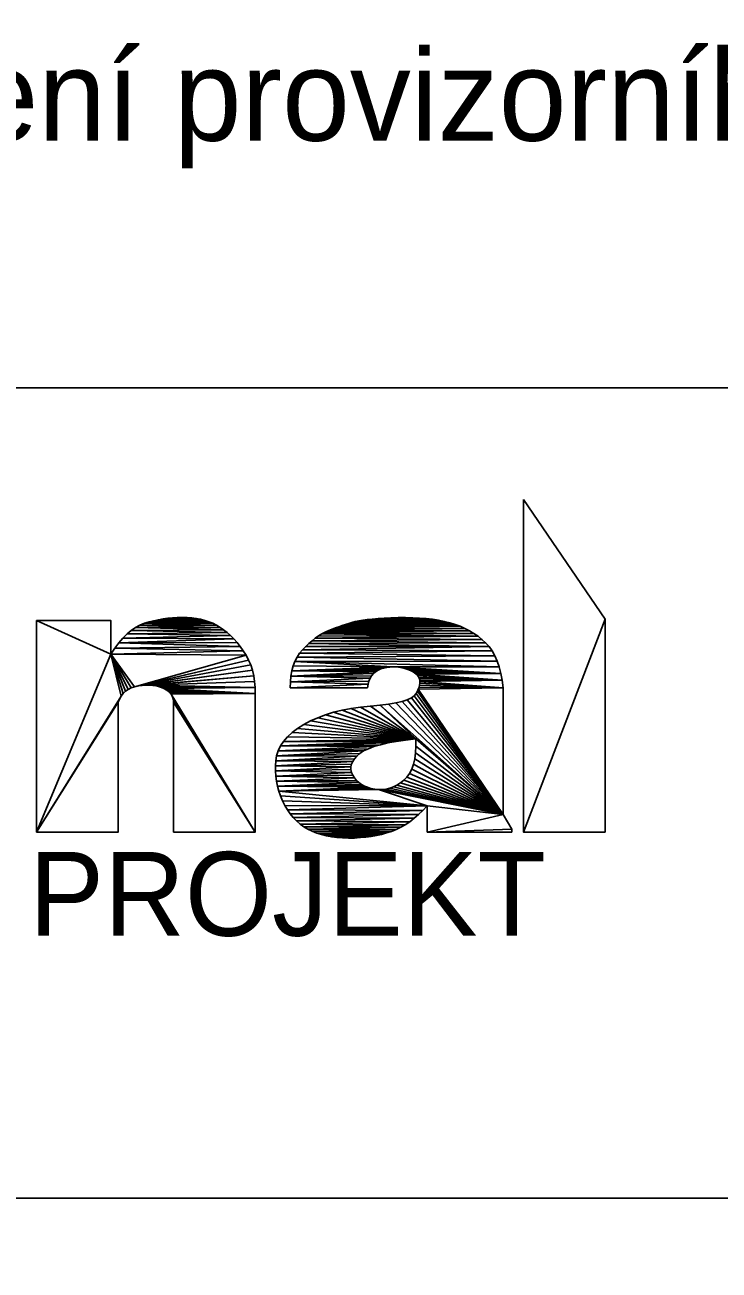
# Model space of a CAD drawing. Extents: x -630 to 5777, y 50 to 2087.
# Drawn here: x -160.3 to -141.25, y 88.03 to 122.18 of the extents above; entities that cross this region are included whole.
import ezdxf

# ---------------------------------------------------------------- set-up
doc = ezdxf.new("R2010")
doc.units = 0
doc.layers.add('Vrstva 1', color=7, linetype='Continuous')
doc.layers.add('Vrstva 50', color=7, linetype='Continuous')

msp = doc.modelspace()

# ---------------------------------------------------------------- linework, layer by layer
for points in [[(-180, 112.226), (-15, 112.226), (-15, 60), (-180, 60)], [(-146.62, 109.158), (-146.62, 100.038), (-144.38, 105.878)], [(-156.509, 105.886), (-156.638, 105.864), (-155.478, 105.876)], [(-155.478, 105.876), (-156.638, 105.864), (-155.363, 105.846)], [(-156.379, 105.904), (-156.509, 105.886), (-155.597, 105.9)], [(-155.597, 105.9), (-156.509, 105.886), (-155.478, 105.876)], [(-156.247, 105.918), (-156.379, 105.904), (-155.721, 105.916)], [(-155.721, 105.916), (-156.379, 105.904), (-155.597, 105.9)], [(-156.115, 105.926), (-156.247, 105.918), (-155.721, 105.916)], [(-155.981, 105.928), (-156.115, 105.926), (-155.849, 105.926)], [(-155.849, 105.926), (-156.115, 105.926), (-155.721, 105.916)], [(-150.905, 105.868), (-151.03, 105.85), (-148.953, 105.848)], [(-150.766, 105.882), (-150.905, 105.868), (-149.119, 105.874)], [(-149.119, 105.874), (-150.905, 105.868), (-148.953, 105.848)], [(-150.611, 105.896), (-150.766, 105.882), (-149.293, 105.894)], [(-149.293, 105.894), (-150.766, 105.882), (-149.119, 105.874)], [(-150.442, 105.906), (-150.611, 105.896), (-149.293, 105.894)], [(-150.258, 105.914), (-150.442, 105.906), (-149.474, 105.91)], [(-149.474, 105.91), (-150.442, 105.906), (-149.293, 105.894)], [(-150.059, 105.92), (-150.258, 105.914), (-149.661, 105.918)], [(-149.661, 105.918), (-150.258, 105.914), (-149.474, 105.91)], [(-149.857, 105.922), (-150.059, 105.92), (-149.661, 105.918)], [(-144.38, 105.878), (-146.62, 100.038), (-144.38, 100.038)], [(-157.94, 104.918), (-157.94, 105.838), (-159.98, 105.838)], [(-159.98, 105.838), (-159.98, 100.038), (-157.94, 104.918)], [(-157.382, 105.57), (-157.498, 105.472), (-154.752, 105.512)], [(-157.263, 105.652), (-157.382, 105.57), (-154.847, 105.586)], [(-154.847, 105.586), (-157.382, 105.57), (-154.752, 105.512)], [(-157.142, 105.716), (-157.263, 105.652), (-155.044, 105.712)], [(-155.044, 105.712), (-157.263, 105.652), (-154.944, 105.654)], [(-154.944, 105.654), (-157.263, 105.652), (-154.847, 105.586)], [(-155.146, 105.764), (-157.142, 105.716), (-155.044, 105.712)], [(-157.018, 105.764), (-157.142, 105.716), (-155.146, 105.764)], [(-156.892, 105.802), (-157.018, 105.764), (-155.146, 105.764)], [(-156.766, 105.836), (-156.892, 105.802), (-155.252, 105.808)], [(-155.252, 105.808), (-156.892, 105.802), (-155.146, 105.764)], [(-156.638, 105.864), (-156.766, 105.836), (-155.363, 105.846)], [(-155.363, 105.846), (-156.766, 105.836), (-155.252, 105.808)], [(-152.058, 105.524), (-152.15, 105.476), (-147.98, 105.486)], [(-151.965, 105.566), (-152.058, 105.524), (-148.1, 105.558)], [(-148.1, 105.558), (-152.058, 105.524), (-147.98, 105.486)], [(-151.871, 105.602), (-151.965, 105.566), (-148.1, 105.558)], [(-151.779, 105.638), (-151.871, 105.602), (-148.226, 105.624)], [(-148.226, 105.624), (-151.871, 105.602), (-148.1, 105.558)], [(-151.687, 105.672), (-151.779, 105.638), (-148.226, 105.624)], [(-151.595, 105.702), (-151.687, 105.672), (-148.358, 105.682)], [(-148.358, 105.682), (-151.687, 105.672), (-148.226, 105.624)], [(-151.505, 105.732), (-151.595, 105.702), (-148.358, 105.682)], [(-151.415, 105.76), (-151.505, 105.732), (-148.497, 105.734)], [(-148.497, 105.734), (-151.505, 105.732), (-148.358, 105.682)], [(-151.325, 105.786), (-151.415, 105.76), (-148.642, 105.778)], [(-148.642, 105.778), (-151.415, 105.76), (-148.497, 105.734)], [(-151.237, 105.81), (-151.325, 105.786), (-148.642, 105.778)], [(-151.141, 105.832), (-151.237, 105.81), (-148.794, 105.816)], [(-148.794, 105.816), (-151.237, 105.81), (-148.642, 105.778)], [(-151.03, 105.85), (-151.141, 105.832), (-148.953, 105.848)], [(-148.953, 105.848), (-151.141, 105.832), (-148.794, 105.816)], [(-157.724, 105.228), (-157.833, 105.082), (-154.393, 105.128)], [(-157.612, 105.358), (-157.724, 105.228), (-154.568, 105.336)], [(-154.568, 105.336), (-157.724, 105.228), (-154.479, 105.236)], [(-154.479, 105.236), (-157.724, 105.228), (-154.393, 105.128)], [(-157.498, 105.472), (-157.612, 105.358), (-154.659, 105.428)], [(-154.659, 105.428), (-157.612, 105.358), (-154.568, 105.336)], [(-154.752, 105.512), (-157.498, 105.472), (-154.659, 105.428)], [(-152.509, 105.212), (-152.596, 105.13), (-147.565, 105.126)], [(-152.421, 105.288), (-152.509, 105.212), (-147.658, 105.23)], [(-147.658, 105.23), (-152.509, 105.212), (-147.565, 105.126)], [(-152.332, 105.358), (-152.421, 105.288), (-147.759, 105.322)], [(-147.759, 105.322), (-152.421, 105.288), (-147.658, 105.23)], [(-152.242, 105.42), (-152.332, 105.358), (-147.866, 105.408)], [(-147.866, 105.408), (-152.332, 105.358), (-147.759, 105.322)], [(-152.15, 105.476), (-152.242, 105.42), (-147.866, 105.408)], [(-147.98, 105.486), (-152.15, 105.476), (-147.866, 105.408)], [(-157.94, 104.918), (-159.98, 100.038), (-157.662, 103.77)], [(-157.833, 105.082), (-157.94, 104.918), (-154.308, 105.012)], [(-154.308, 105.012), (-157.94, 104.918), (-154.229, 104.888)], [(-157.94, 104.918), (-157.291, 104.024), (-154.229, 104.888)], [(-157.94, 104.918), (-157.385, 103.994), (-157.291, 104.024)], [(-157.94, 104.918), (-157.469, 103.952), (-157.385, 103.994)], [(-157.94, 104.918), (-157.543, 103.902), (-157.469, 103.952)], [(-157.94, 104.918), (-157.607, 103.84), (-157.543, 103.902)], [(-157.94, 104.918), (-157.662, 103.77), (-157.607, 103.84)], [(-154.393, 105.128), (-157.833, 105.082), (-154.308, 105.012)], [(-154.229, 104.888), (-157.291, 104.024), (-154.161, 104.758)], [(-152.763, 104.942), (-152.832, 104.836), (-147.407, 104.876)], [(-147.407, 104.876), (-152.832, 104.836), (-147.343, 104.73)], [(-152.682, 105.04), (-152.763, 104.942), (-147.481, 105.008)], [(-147.481, 105.008), (-152.763, 104.942), (-147.407, 104.876)], [(-152.596, 105.13), (-152.682, 105.04), (-147.565, 105.126)], [(-147.565, 105.126), (-152.682, 105.04), (-147.481, 105.008)], [(-154.161, 104.758), (-157.291, 104.024), (-157.187, 104.046)], [(-154.161, 104.758), (-157.187, 104.046), (-154.104, 104.622)], [(-154.104, 104.622), (-157.187, 104.046), (-154.058, 104.478)], [(-152.938, 104.594), (-152.975, 104.46), (-150.209, 104.57)], [(-150.209, 104.57), (-152.975, 104.46), (-150.291, 104.566)], [(-150.291, 104.566), (-152.975, 104.46), (-150.373, 104.554)], [(-150.373, 104.554), (-152.975, 104.46), (-150.454, 104.536)], [(-150.454, 104.536), (-152.975, 104.46), (-150.535, 104.512)], [(-150.535, 104.512), (-152.975, 104.46), (-150.611, 104.48)], [(-152.89, 104.72), (-152.938, 104.594), (-150.209, 104.57)], [(-152.832, 104.836), (-152.89, 104.72), (-147.343, 104.73)], [(-147.343, 104.73), (-152.89, 104.72), (-147.288, 104.568)], [(-152.89, 104.72), (-150.209, 104.57), (-147.288, 104.568)], [(-150.209, 104.57), (-150.127, 104.568), (-147.288, 104.568)], [(-150.127, 104.568), (-150.044, 104.56), (-147.288, 104.568)], [(-147.288, 104.568), (-150.044, 104.56), (-147.243, 104.392)], [(-150.044, 104.56), (-149.96, 104.546), (-147.243, 104.392)], [(-149.96, 104.546), (-149.876, 104.524), (-147.243, 104.392)], [(-149.876, 104.524), (-149.796, 104.498), (-147.243, 104.392)], [(-154.058, 104.478), (-157.187, 104.046), (-157.081, 104.058)], [(-154.058, 104.478), (-157.081, 104.058), (-154.022, 104.328)], [(-154.022, 104.328), (-157.081, 104.058), (-156.98, 104.066)], [(-154.022, 104.328), (-156.98, 104.066), (-156.885, 104.066)], [(-154.022, 104.328), (-156.885, 104.066), (-153.998, 104.17)], [(-153.998, 104.17), (-156.885, 104.066), (-153.984, 104.008)], [(-153.016, 104.16), (-153.02, 103.998), (-150.885, 104.094)], [(-153.001, 104.314), (-153.016, 104.16), (-150.828, 104.26)], [(-150.828, 104.26), (-153.016, 104.16), (-150.861, 104.182)], [(-150.861, 104.182), (-153.016, 104.16), (-150.885, 104.094)], [(-152.975, 104.46), (-153.001, 104.314), (-150.678, 104.438)], [(-150.678, 104.438), (-153.001, 104.314), (-150.737, 104.388)], [(-150.737, 104.388), (-153.001, 104.314), (-150.787, 104.328)], [(-150.787, 104.328), (-153.001, 104.314), (-150.828, 104.26)], [(-150.611, 104.48), (-152.975, 104.46), (-150.678, 104.438)], [(-149.796, 104.498), (-149.724, 104.47), (-147.243, 104.392)], [(-149.724, 104.47), (-149.662, 104.44), (-147.243, 104.392)], [(-149.662, 104.44), (-149.608, 104.408), (-147.243, 104.392)], [(-149.608, 104.408), (-149.563, 104.374), (-147.243, 104.392)], [(-147.243, 104.392), (-149.563, 104.374), (-147.207, 104.202)], [(-149.563, 104.374), (-149.526, 104.338), (-147.207, 104.202)], [(-149.526, 104.338), (-149.499, 104.3), (-147.207, 104.202)], [(-149.499, 104.3), (-149.48, 104.26), (-147.207, 104.202)], [(-149.48, 104.26), (-149.468, 104.216), (-147.207, 104.202)], [(-149.468, 104.216), (-149.463, 104.17), (-147.207, 104.202)], [(-149.463, 104.17), (-149.464, 104.122), (-147.18, 103.998)], [(-147.207, 104.202), (-149.463, 104.17), (-147.18, 103.998)], [(-156.885, 104.066), (-156.794, 104.062), (-153.984, 104.008)], [(-156.794, 104.062), (-156.709, 104.05), (-153.984, 104.008)], [(-156.709, 104.05), (-156.63, 104.032), (-153.984, 104.008)], [(-156.63, 104.032), (-156.555, 104.008), (-153.984, 104.008)], [(-156.555, 104.008), (-156.486, 103.978), (-153.984, 104.008)], [(-153.984, 104.008), (-156.486, 103.978), (-153.98, 103.838)], [(-156.486, 103.978), (-156.424, 103.944), (-153.98, 103.838)], [(-156.424, 103.944), (-156.37, 103.906), (-153.98, 103.838)], [(-156.37, 103.906), (-156.324, 103.864), (-153.98, 103.838)], [(-156.324, 103.864), (-156.287, 103.818), (-153.98, 103.838)], [(-153.98, 103.838), (-156.287, 103.818), (-153.98, 100.038)], [(-156.287, 103.818), (-156.258, 103.768), (-153.98, 100.038)], [(-150.885, 104.094), (-153.02, 103.998), (-150.9, 103.998)], [(-149.564, 103.838), (-149.615, 103.776), (-147.18, 100.518)], [(-149.532, 103.9), (-149.564, 103.838), (-147.18, 100.518)], [(-149.506, 103.96), (-149.532, 103.9), (-147.18, 100.518)], [(-149.486, 104.016), (-149.506, 103.96), (-147.18, 103.998)], [(-147.18, 103.998), (-149.506, 103.96), (-147.18, 100.518)], [(-149.472, 104.07), (-149.486, 104.016), (-147.18, 103.998)], [(-149.464, 104.122), (-149.472, 104.07), (-147.18, 103.998)], [(-157.662, 103.77), (-159.98, 100.038), (-157.706, 103.688)], [(-157.706, 103.688), (-159.98, 100.038), (-157.74, 103.598)], [(-157.74, 103.598), (-159.98, 100.038), (-157.74, 100.038)], [(-156.258, 103.768), (-156.237, 103.716), (-153.98, 100.038)], [(-156.237, 103.716), (-156.225, 103.658), (-153.98, 100.038)], [(-156.225, 103.658), (-156.22, 103.598), (-153.98, 100.038)], [(-156.22, 103.598), (-156.22, 100.038), (-153.98, 100.038)], [(-150.819, 103.496), (-151.091, 103.468), (-149.576, 102.594)], [(-150.556, 103.52), (-150.819, 103.496), (-149.576, 102.594)], [(-150.323, 103.55), (-150.556, 103.52), (-147.18, 100.518)], [(-150.556, 103.52), (-149.576, 102.594), (-147.18, 100.518)], [(-150.121, 103.584), (-150.323, 103.55), (-147.18, 100.518)], [(-149.949, 103.624), (-150.121, 103.584), (-147.18, 100.518)], [(-149.807, 103.67), (-149.949, 103.624), (-147.18, 100.518)], [(-149.696, 103.72), (-149.807, 103.67), (-147.18, 100.518)], [(-149.615, 103.776), (-149.696, 103.72), (-147.18, 100.518)], [(-152.266, 103.176), (-152.464, 103.086), (-149.576, 102.594)], [(-152.055, 103.256), (-152.266, 103.176), (-149.576, 102.594)], [(-151.833, 103.326), (-152.055, 103.256), (-149.576, 102.594)], [(-151.598, 103.384), (-151.833, 103.326), (-149.576, 102.594)], [(-151.35, 103.432), (-151.598, 103.384), (-149.576, 102.594)], [(-151.091, 103.468), (-151.35, 103.432), (-149.576, 102.594)], [(-152.819, 102.878), (-152.967, 102.766), (-149.576, 102.594)], [(-152.65, 102.986), (-152.819, 102.878), (-149.576, 102.594)], [(-152.464, 103.086), (-152.65, 102.986), (-149.576, 102.594)], [(-150.11, 102.526), (-153.287, 102.4), (-150.339, 102.484)], [(-153.201, 102.526), (-153.287, 102.4), (-150.11, 102.526)], [(-150.339, 102.484), (-153.287, 102.4), (-150.544, 102.436)], [(-153.095, 102.648), (-153.201, 102.526), (-149.576, 102.594)], [(-149.576, 102.594), (-153.201, 102.526), (-149.855, 102.562)], [(-149.855, 102.562), (-153.201, 102.526), (-150.11, 102.526)], [(-152.967, 102.766), (-153.095, 102.648), (-149.576, 102.594)], [(-149.576, 102.594), (-149.571, 102.394), (-147.18, 100.518)], [(-153.396, 102.134), (-153.419, 101.994), (-151.191, 102.124)], [(-151.191, 102.124), (-153.419, 101.994), (-151.257, 102.052)], [(-153.352, 102.27), (-153.396, 102.134), (-151.005, 102.264)], [(-151.005, 102.264), (-153.396, 102.134), (-151.108, 102.196)], [(-151.108, 102.196), (-153.396, 102.134), (-151.191, 102.124)], [(-153.287, 102.4), (-153.352, 102.27), (-150.723, 102.384)], [(-150.723, 102.384), (-153.352, 102.27), (-150.876, 102.326)], [(-150.876, 102.326), (-153.352, 102.27), (-151.005, 102.264)], [(-150.544, 102.436), (-153.287, 102.4), (-150.723, 102.384)], [(-149.58, 102.212), (-149.602, 102.046), (-147.18, 100.518)], [(-149.571, 102.394), (-149.58, 102.212), (-147.18, 100.518)], [(-153.419, 101.994), (-153.427, 101.854), (-151.306, 101.978)], [(-151.306, 101.978), (-153.427, 101.854), (-151.338, 101.904)], [(-151.338, 101.904), (-153.427, 101.854), (-151.354, 101.828)], [(-153.427, 101.854), (-153.426, 101.714), (-151.354, 101.828)], [(-151.354, 101.828), (-153.426, 101.714), (-151.353, 101.752)], [(-151.257, 102.052), (-153.419, 101.994), (-151.306, 101.978)], [(-149.636, 101.898), (-149.684, 101.764), (-147.18, 100.518)], [(-149.602, 102.046), (-149.636, 101.898), (-147.18, 100.518)], [(-151.353, 101.752), (-153.426, 101.714), (-151.335, 101.676)], [(-153.426, 101.714), (-153.416, 101.574), (-151.335, 101.676)], [(-151.335, 101.676), (-153.416, 101.574), (-151.301, 101.598)], [(-151.301, 101.598), (-153.416, 101.574), (-151.254, 101.524)], [(-153.416, 101.574), (-153.397, 101.436), (-151.254, 101.524)], [(-151.254, 101.524), (-153.397, 101.436), (-151.199, 101.456)], [(-151.199, 101.456), (-153.397, 101.436), (-151.136, 101.398)], [(-153.397, 101.436), (-153.369, 101.3), (-151.136, 101.398)], [(-149.904, 101.46), (-149.997, 101.388), (-147.18, 100.518)], [(-149.818, 101.544), (-149.904, 101.46), (-147.18, 100.518)], [(-149.744, 101.646), (-149.818, 101.544), (-147.18, 100.518)], [(-149.684, 101.764), (-149.744, 101.646), (-147.18, 100.518)], [(-151.136, 101.398), (-153.369, 101.3), (-151.065, 101.346)], [(-151.065, 101.346), (-153.369, 101.3), (-150.986, 101.302)], [(-150.986, 101.302), (-153.369, 101.3), (-150.9, 101.266)], [(-153.369, 101.3), (-153.332, 101.164), (-150.9, 101.266)], [(-150.9, 101.266), (-153.332, 101.164), (-150.805, 101.238)], [(-150.805, 101.238), (-153.332, 101.164), (-150.702, 101.218)], [(-150.702, 101.218), (-153.332, 101.164), (-150.596, 101.208)], [(-150.596, 101.208), (-153.332, 101.164), (-149.26, 100.758)], [(-153.332, 101.164), (-153.286, 101.03), (-149.26, 100.758)], [(-150.596, 101.208), (-149.26, 100.758), (-147.18, 100.518)], [(-150.492, 101.208), (-150.596, 101.208), (-147.18, 100.518)], [(-150.389, 101.22), (-150.492, 101.208), (-147.18, 100.518)], [(-150.289, 101.246), (-150.389, 101.22), (-147.18, 100.518)], [(-150.19, 101.282), (-150.289, 101.246), (-147.18, 100.518)], [(-150.093, 101.328), (-150.19, 101.282), (-147.18, 100.518)], [(-149.997, 101.388), (-150.093, 101.328), (-147.18, 100.518)], [(-153.286, 101.03), (-153.231, 100.896), (-149.26, 100.758)], [(-153.231, 100.896), (-153.168, 100.768), (-149.26, 100.758)], [(-153.168, 100.768), (-153.098, 100.65), (-149.26, 100.758)], [(-149.26, 100.758), (-153.098, 100.65), (-149.378, 100.634)], [(-149.26, 100.758), (-149.26, 100.038), (-147.18, 100.518)], [(-153.098, 100.65), (-153.021, 100.538), (-149.378, 100.634)], [(-149.378, 100.634), (-153.021, 100.538), (-149.496, 100.52)], [(-153.021, 100.538), (-152.937, 100.438), (-149.496, 100.52)], [(-149.496, 100.52), (-152.937, 100.438), (-149.617, 100.418)], [(-152.937, 100.438), (-152.847, 100.344), (-149.617, 100.418)], [(-149.617, 100.418), (-152.847, 100.344), (-149.739, 100.324)], [(-147.18, 100.518), (-149.26, 100.038), (-146.94, 100.118)], [(-152.847, 100.344), (-152.749, 100.26), (-149.739, 100.324)], [(-149.739, 100.324), (-152.749, 100.26), (-149.863, 100.242)], [(-152.749, 100.26), (-152.645, 100.186), (-149.863, 100.242)], [(-149.863, 100.242), (-152.645, 100.186), (-149.988, 100.17)], [(-152.645, 100.186), (-152.533, 100.12), (-149.988, 100.17)], [(-149.988, 100.17), (-152.533, 100.12), (-150.115, 100.108)], [(-152.533, 100.12), (-152.415, 100.062), (-150.115, 100.108)], [(-150.115, 100.108), (-152.415, 100.062), (-150.244, 100.058)], [(-152.415, 100.062), (-152.291, 100.012), (-150.244, 100.058)], [(-146.94, 100.118), (-149.26, 100.038), (-146.94, 100.038)], [(-150.244, 100.058), (-152.291, 100.012), (-150.375, 100.014)], [(-150.375, 100.014), (-152.291, 100.012), (-150.511, 99.976)], [(-152.291, 100.012), (-152.161, 99.97), (-150.511, 99.976)], [(-150.511, 99.976), (-152.161, 99.97), (-150.652, 99.946)], [(-152.161, 99.97), (-152.024, 99.936), (-150.652, 99.946)], [(-150.652, 99.946), (-152.024, 99.936), (-150.796, 99.92)], [(-152.024, 99.936), (-151.882, 99.908), (-150.796, 99.92)], [(-150.796, 99.92), (-151.882, 99.908), (-150.945, 99.9)], [(-151.882, 99.908), (-151.733, 99.888), (-150.945, 99.9)], [(-150.945, 99.9), (-151.733, 99.888), (-151.098, 99.886)], [(-151.733, 99.888), (-151.579, 99.878), (-151.098, 99.886)], [(-151.098, 99.886), (-151.579, 99.878), (-151.256, 99.876)], [(-151.579, 99.878), (-151.418, 99.874), (-151.256, 99.876)]]:
    msp.add_lwpolyline(points, close=True)
at = {"layer": 'Vrstva 1'}
msp.add_line((-65, 90), (-180, 90), dxfattribs=at)

# ---------------------------------------------------------------- texts
msp.add_text('PROJEKT', height=2.299).set_placement((-160.18, 97.194))
at = {"layer": 'Vrstva 50'}
msp.add_text('Červeně řešení provizorního SZZ. Fialově venkovní prvky z definitivního SZZ využité v provizorním SZZ.', height=2.500002, dxfattribs=at).set_placement((-180, 119))

doc.saveas('drawing.dxf')
